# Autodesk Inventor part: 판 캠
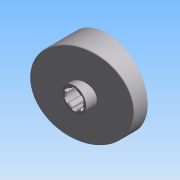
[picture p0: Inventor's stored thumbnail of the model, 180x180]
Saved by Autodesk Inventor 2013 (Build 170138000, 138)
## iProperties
Company: 한국ATC센터
Created: 2014-07
Part Number: 판 캠
Document SubType Name: 모델링
Designer: KYOUNG IL JANG
Material: 강철
Mass: 681.586 g
Surface Area: 331.301 cm^2
Volume: 86.8262 cm^3
Density: 7.85 g/cm^3
변환 표준: STEP AP214IS
파일 이름: C:\Users\SeoGD\Desktop\?쒗뿕\??stp
전처리기: Build: 253, Release: 2010 SP1 - Date: Wed 07/29/2009
전송 단위: 밀리미터
불확실성: 0.01
Author: KYOUNG IL JANG
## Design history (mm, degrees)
node "작업 평면4"
sketch "스케치1"
  geometry: C1 r 44.5 at (0, 0); 1 further point
  constraints: 1 centre point, 1 coincident
  dimensions: "d25" = 89 diameter of C1
extrude "돌출1" new body sketch "스케치1" distance "d1" = 40; taper "d2" = 0 deg
sketch "스케치2"
  geometry: L1 (-44.5, 15)-(44.5, 38.847); L2 (-44.5, 0)-(-44.5, 40) reference; L3 (-44.5, 40)-(44.5, 40) reference; L4 (44.5, 0)-(44.5, 40) reference; 1 further point
  constraints: 2 end point, 2 point on line
  dimensions: "d26" = 15 distance of L2.start L1.start; "d27" = 75 deg angle of L1 L2
extrude "돌출2" cut sketch "스케치2" stored distance "d5" = 40; taper "d6" = 0 deg
node "작업 평면1"
sketch "스케치3"
  geometry: C1 r 13 at (0, 0); 1 further point
  constraints: 1 centre point, 1 coincident
  dimensions: "d9" = 26 diameter of C1
extrude "돌출3" join sketch "스케치3" distance "d10" = 38; taper "d11" = 0 deg
hole "구멍1" diameter "d14" = 18; stored, may be unused: countersink angle "d18" = 90 deg, drill point angle "d20" = 118 deg; dims "d12" = 10, "d13" = 10, "d15" = 6, "d16" = 4, "d17" = 2, "d19" = 8
feature "쉘2" dims "d29" = 5
sketch "스케치6"
  geometry: C1 r 17.5 at (0, 0); C2 r 14 at (0, 0) reference; 1 further point
  constraints: 1 centre point, 1 coincident
  dimensions: "d28" = 35 diameter of C1
extrude "돌출4" join sketch "스케치6" stored distance "d30" = 38; taper "d31" = 0 deg
fillet "모깎기1" dims "d32" = 3
chamfer "모따기1" distance "d21" = 1; stored, may be unused: second distance "d22" = 2, angle "d23" = 45 deg
feature "리브1" dims "d34" = 5, "d35" = 1, "d36" = 0
fillet "모깎기2" dims "d37" = 3
sketch "스케치8"
  geometry: L1 (2.5, 10.712)-(2.5, 8.646); L2 (-2.5, 10.712)-(-2.5, 8.646); A1 r 11 centre (0, 0) between (2.5, 10.712) and (-2.5, 10.712); A2 r 9 centre (0, 0) between (2.5, 8.646) and (-2.5, 8.646) reference; 1 further point
  constraints: 4 end point, 4 point on circle, 2 parallel, 1 centre point, 1 coincident, 1 vertical
  dimensions: "d41" = 22 diameter of A1; "d42" = 5 distance between parallel lines of L1 L2
extrude "돌출5" cut sketch "스케치8" stored distance "d43" = 38; taper "d44" = 0 deg
fillet "모깎기3" dims "d48" = 1
node "솔리드1"
node "솔리드 본체"
node "곡면 본체"
pattern_circular "원형 패턴1" dims angle "d39" = 360 deg
pattern_circular "원형 패턴2" dims angle "d46" = 360 deg
node "솔리드2"
sketch "스케치7"
  geometry: L1 (-12.374, 12.374)-(-27.931, 27.931); A1 r 39.5 centre (0, 0) between (-27.931, 27.931) and (0, 39.5) reference; 2 further points
  constraints: 2 end point, 2 point on circle, 1 point on line, 1 vertical alignment, 2 other
  dimensions: "d33" = 45 deg dimension on point (0, 0) L1.start A1.end
